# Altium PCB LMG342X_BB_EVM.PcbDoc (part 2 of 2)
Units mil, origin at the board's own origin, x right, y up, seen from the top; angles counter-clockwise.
Board outline 6400 x 3655 mil, 2 copper layers (Top Layer, Bottom Layer), stack 61.2 mil thick; 157 components, 63 nets, 278 pads, 411 vias.
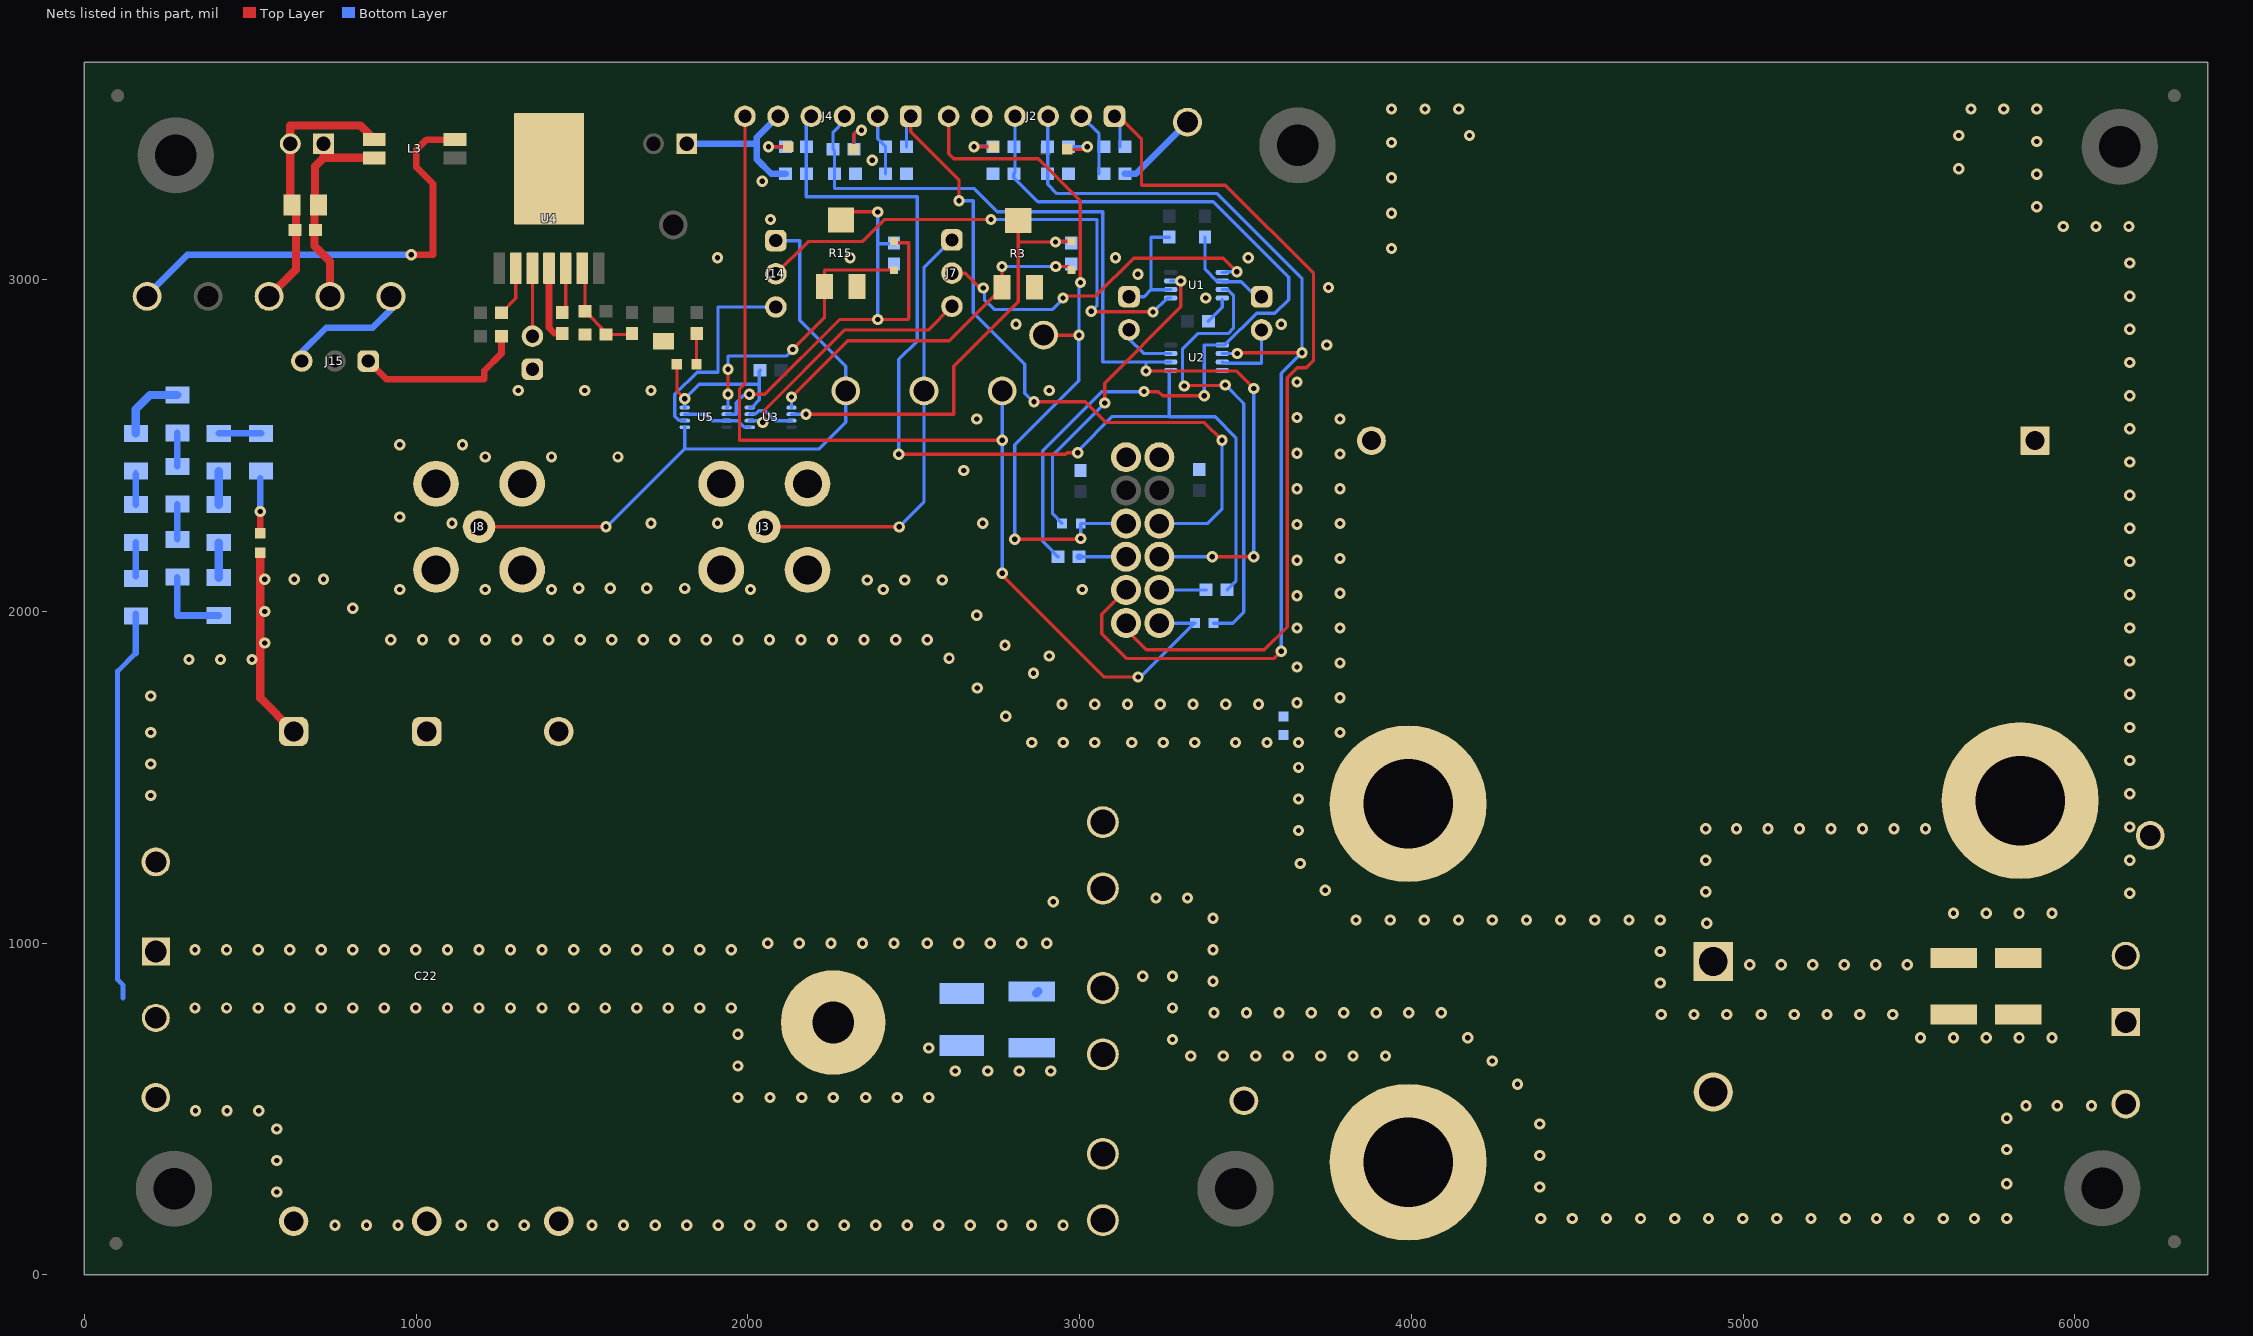
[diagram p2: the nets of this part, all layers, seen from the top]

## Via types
v1: diameter 34, hole 16, Top Layer to Bottom Layer, 411 vias

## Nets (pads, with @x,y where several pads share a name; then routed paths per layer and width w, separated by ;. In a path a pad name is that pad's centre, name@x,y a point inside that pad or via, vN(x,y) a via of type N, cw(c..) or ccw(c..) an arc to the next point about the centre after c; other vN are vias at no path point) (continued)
AGND: 5V_EN.2 AGND1.1 AGND2.1 C1.1 C2.1 C3.1 C5.2 C6.2 C8.2 C9.1 C10.2 C12.2 C14.2 C15.2 C17.2 C20.2 C21.2 C23.2 J2.5 J3.2 J3.3 J3.4 J3.5 J4.5 J8.2 J8.3 J8.4 J8.5 J12.1 J13.1 J15.1 J19.1 J25.1 L3.2 R9.1 R26.1 U1.4 U2.4 U3.4 U4.4 U4.8 U5.4 | length 3439.7
  Top Layer w10: 1416.97,2838.9 C20.2@1440.47,2838.9 ; 5V_EN.2@1785.94,2745 1785.94,2665.38 v1(1809.68,2641.65) v1@1809.68,2643.35
  Top Layer w20: J15.1@855.18,2755 910.18,2700 1205,2700 1205,2725.91 1256.97,2777.87 C15.2@1256.97,2830 ; v1(985,3075) 1050.47,3075 1050.47,3289.53 1000,3340 1000,3391.06 1031.5,3422.56 L3.2@1116.93,3422.56 ; U4.4@1400.47,3030 1400.47,2855.39 1416.97,2838.9
  Bottom Layer w10: U5.4@1809.68,2614.53 v1(1809.68,2641.65) 1853.03,2685 2034.28,2685 ; U3.4@2005.33,2614.53 2011.18,2614.53 2034.28,2637.63 2034.28,2685 ; C9.1@2036.83,2727.28 2034.28,2724.73 2034.28,2685 ; C1.1@3387.99,2875 3430,2917.01 U1.4@3430,2940
  Bottom Layer w20: AGND2.1@190,2955.02 309.98,3075 v1(985,3075) ; J12.1@1815.47,3410 2022.79,3410 ; J4.5@2091,3492.93 2029.03,3430.97 2027,3428.94 2027,3363 2070.42,3319.58 C14.2@2113.2,3319.58 ; C2.1@3136.5,3319.58 3169.58,3319.58 AGND1.1@3325,3475
  other v1: 2946.49,1720 3045.29,1720 3144.09,1720 3242.89,1720 3341.69,1720 3440.48,1720 3539.28,1720 3655,1725 2861.14,1813.56 3655,1832.44 2908,1866 2775,1898.56 3655.12,1949.99 2690,1988.56 3655.3,2047.33 950,2066.07 1208,2066 1408,2066 2008,2066 2408,2066 3008,2066 1490,2070.26 1585,2070.26 1695,2070.26 1809.68,2069.61 2359.68,2095.11 2472.9,2095.11 2586.12,2095.11 3655.3,2154.78 3655.3,2262.22 1108,2266 1708,2266 1908,2266 2708,2266 950,2284.55 3655.3,2369.66 2650.25,2424.79 1208,2466 1408,2466 1608,2466 3655.3,2477.11 950,2503.03 1139.58,2503.03 2690,2580 3655.3,2584.55 1308,2666 1508,2666 1708,2666 2908,2666 3655.3,2692 3745,2803.39 2808,2866 3608,2866 3380.32,2945.02 3750,2976.75 3175.56,3016.57 1908,3066 2308,3066 3108,3066 3508,3066 2067.96,3181.64 2043.37,3297.3 2374.49,3360.13
HS_FET_FAULTZ_2: C12.1 J2.4 R1.1 R7.2 U2.1 | length 2576.6
  Top Layer w10: v1(3194.13,2662.87) 3237.13,2662.87 3249.87,2650.13 v1(3375.49,2650.13)
  Bottom Layer w10: J2.4@2805,3492.93 2805,3323.08 C12.1@2801.5,3319.58 2801.5,3307.87 2874.37,3235 3402.25,3235 3630,3007.25 3630,2940 3588.76,2898.76 3533.41,2898.76 3438.04,2803.39 U2.1@3430,2803.39 3375.87,2803.39 3375.87,2650.5 v1(3375.49,2650.13) ; R7.2@2935,2165 2934.02,2165 2920.31,2178.7 2920.31,2179.69 2888.49,2211.52 2888.49,2484.8 3066.56,2662.87 v1(3194.13,2662.87)
HS_FET_OCZ_2: C5.1 J2.3 J23.1 R29.1 U2.2 | length 3224.6
  Top Layer w10: J23.1@3140,2065 3066.56,1991.56 3066.56,1932.9 3141.34,1858.13 3585.66,1858.13 v1(3607.6,1880.07) ; v1(3475,2777.8) 3477.2,2780 v1(3670,2780)
  Bottom Layer w10: J2.3@2905,3492.93 2903.5,3491.44 R29.1@2903.5,3401.05 C5.1@2903.5,3319.58 2903.5,3288.01 2931.51,3260 3415,3260 3670,3005 v1(3670,2780) 3607.6,2717.6 v1(3607.6,1880.07) ; U2.2@3430,2777.8 v1(3475,2777.8)
HS_FET_PWM_2: HS_FET_PWM.1 J2.6 J21.1 R2.2 | length 2167.2
  Top Layer w10: J2.6@2605,3492.93 2605,3380 2620,3365 2875.75,3365 3002.27,3238.49 v1(3002.27,2991.8) ; v1(2804.62,2218) 2805,2217.62 2805.38,2218 3003.54,2218 v1(3003.54,2219.82) ; HS_FET_PWM.1@2891.38,2833.13 v1(2997.99,2833.13)
  Bottom Layer w10: v1(2804.62,2218) 2804.62,2502.6 2997.01,2695 2997.01,2832.15 v1(2997.99,2833.13) 2997.99,2979.81 3004.47,2986.28 2998.95,2991.8 v1(3002.27,2991.8) ; v1(3003.54,2219.82) 3003.36,2220 R2.2@3003.36,2265 J21.1@3140,2265
HS_FET_TEMP_2: J2.1 J24.1 R8.1 | length 2649.2
  Top Layer w10: J2.1@3105,3492.93 3117.73,3492.93 3186.53,3424.14 3186.53,3285 3439,3285 3705,3019 3705,2757.57 3682.43,2735 3655.76,2735 3625.42,2704.67 3625.42,1953.23 3557.2,1885 3200.39,1885 3140,1945.39 J24.1@3140,1965
  Bottom Layer w10: J2.1@3105,3492.93 3121.5,3476.44 R8.1@3121.5,3401.05
HS_FET_TEMP_FILT_2: C2.2 J2.2 R8.2 | length 195.5
  Bottom Layer w10: J2.2@3005,3492.93 3058.5,3439.43 3058.5,3401.05 C2.2@3058.5,3319.58
HVBUS_2: C22.2 C22.4 CIN3.1 CIN4.1 HVBUS1.1 HVBUS2.1 HVIN.1 J1.2 R10.2 | length 1187
  Bottom Layer w15: 115.64,835 115.64,874.36 100,890 100,1820 154.92,1874.92
  Bottom Layer w20: 154.92,1874.92 R10.2@154.92,1992.78
  other v1: 755,150 850.1,150 945.19,150 1135.39,150 1230.49,150 1325.58,150 1530,150 1625.1,150 1720.19,150 1815.29,150 1910.39,150 2005.49,150 2100.58,150 2195,150 2290.1,150 2385.19,150 2480.29,150 2575.39,150 2670.49,150 2765.58,150 2855,150 2950.1,150 580,250 580,345.1 580,440.19 334.81,495 429.9,495 525,495 1969.74,535 2066.81,535 2161.9,535 2257,535 2354.81,535 2449.9,535 2545,535 2625,615 2722.81,615 2817.9,615 2913,615 1969.74,630.1 2545,684.19 1969.74,725.19 333.35,805 428.44,805 523.54,805 618.64,805 713.74,805 808.83,805 903.93,805 999.03,805 1094.13,805 1189.22,805 1284.32,805 1379.42,805 1474.51,805 1569.61,805 1664.71,805 1759.81,805 1854.9,805 1950,805
HVOUT_2: C25.1 COUT3.1 COUT4.1 HVOUT.1 J9.2 J18.1 L2.1
  other v1: 5020,935 5115,935 5210,935 5305,935 5400,935 5495,935 4890,1060 5634,1090 5733,1090 5832,1090 5931,1090 6165.5,1150.5 4887,1155 4887,1250 6165.5,1250.5 4887,1345 4980,1345 5075,1345 5170,1345 5265,1345 5360,1345 5455,1345 5550,1345 6165.5,1350.5 6165.5,1450.5 6165.5,1550.5 6165.5,1650.5 6165.5,1750.5 6165.5,1850.5 6165.5,1950.5 6165.5,2050.5 6165.5,2150.5 6165.5,2250.5 6165.5,2350.5 6165.5,2450.5 6165.5,2550.5 6165.5,2650.5 6165.5,2750.5 6165.5,2850.5 6165.5,2950.5 6165.5,3050.5 5965,3160.5 6064,3160.5 6163,3160.5 5885,3220 5885,3318.33 5650,3335 5885,3416.67 5650,3435 5687,3515 5786,3515 5885,3515
LS_FET_FAULTZ_2: C14.1 J4.4 R5.1 R21.2 U2.5 | length 3098.9
  Top Layer w10: v1(2455,2473.66) 2957.47,2473.66 2962.27,2478.47 v1(2994.47,2478.47)
  Bottom Layer w10: J4.4@2191,3492.93 2176.2,3478.13 R5.1@2176.2,3401.06 C14.1@2176.2,3319.58 2176.2,3250 2510,3250 2510,2814.76 2455,2759.76 v1(2455,2473.66) v1@2446.34,2465 ; v1(2994.47,2478.47) 2994.47,2483.63 3098.71,2587.87 3270,2587.87 ; U2.5@3274.49,2726.61 3275,2726.1 3270,2721.1 3270,2587.87 ; R21.2@3444.32,2065 3445.31,2065 3459.01,2078.7 3459.01,2079.69 3471.05,2091.72 3471.05,2524.26 3408.45,2586.85 3271.02,2586.85 3270,2587.87
LS_FET_OCZ_2: C21.1 J4.3 J28.1 R30.1 U2.6 | length 2895.7
  Top Layer w10: v1(3200,2725) 3472.34,2725 v1(3525,2672.34) ; v1(3400,2165) v1(3525,2165)
  Bottom Layer w10: J4.3@2291,3492.93 2291,3479.71 2256.47,3445.18 R30.1@2256.47,3392.93 2261,3388.41 C21.1@2261,3319.58 2261,3275 2681.82,3275 2751.82,3205 3070,3205 3070,2752.2 3200,2752.2 ; v1(3200,2725) 3200,2752.2 ; J28.1@3240,2165 v1(3400,2165) ; U2.6@3274.49,2752.2 3200,2752.2 ; v1(3525,2165) v1(3525,2672.34)
LS_FET_PWM_2: J4.6 J30.1 LS_FET_PWM.1 R4.2 | length 3217.8
  Top Layer w10: J4.6@1991,3492.93 1991,2686 1974.53,2669.53 1974.53,2515.78 v1(2766.51,2515.78) ; v1(2766.51,2115.3) 2766.51,2109.87 3073.99,1802.38 v1(3176.2,1802.38)
  Bottom Layer w10: v1(2766.51,2115.3) LS_FET_PWM.1@2766.51,2665 ; J30.1@3240,1965 R4.2@3345,1965 ; R4.2@3347.3,1965.01 R4.2@3345.01,1965.01 ; v1@3182.38,1802.38 v1(3176.2,1802.38) v1@3182.38,1802.38 ; v1@3182.38,1802.38 R4.2@3345,1965
LS_FET_TEMP_2: J4.1 J27.1 R27.1 | length 2167.1
  Top Layer w10: J4.1@2491,3492.93 2491,3446.01 2636.51,3300.5 v1(2636.51,3238.49) ; v1(2862.51,2632.17) 3016.79,2632.17 3079.47,2569.48 3375.59,2569.48 v1(3429.29,2515.78)
  Bottom Layer w10: R27.1@2477.83,3400.99 2477.83,3479.77 J4.1@2491,3492.93 ; v1(2636.51,3238.49) 2679.59,3238.49 2679.59,2900.57 2834.62,2745.54 2834.62,2658.1 v1@2861.53,2631.19 ; J27.1@3240,2265 3385.29,2265 3429.29,2309 v1(3429.29,2515.78)
LS_FET_TEMP_FILT_2: C3.2 J4.2 R27.2 | length 183.3
  Bottom Layer w10: J4.2@2391,3492.93 2391,3424.83 R27.2@2414.84,3400.99 C3.2@2414.84,3319.51
Net5V_EN_1: 5V_EN.1 R31.1 | length 93.7
  Top Layer w10: 5V_EN.1@1845,2745 1845,2838.03 R31.1@1845.47,2838.5
NetACMGND_1: ACMGND.1 C18.2 C19.2 J6.1 L3.4 | length 652.7
  Top Layer w25: J6.1@720.47,3410 720.47,3367.44 ; ACMGND.1@740.18,2950 740.18,3054.82 693.47,3101.53 693.47,3150 693.47,3213 C19.2@705.47,3225 695,3235.47 695,3341.97 720.47,3367.44 ; L3.4@874.02,3367.44 720.47,3367.44
NetC10_1: C10.1 D1.1 R3.2 U3.6 | length 1369.4
  Top Layer w10: v1(2174.84,2594.84) 2620,2594.84 2620,2739.17 2815,2934.17 2815,3115 ; R3.2@2815,3178.41 2815,3115 ; D1.1@2975,3116.1 2925,3116.1 v1(2927.14,3113.96) 2816.04,3113.96 2815,3115
  Bottom Layer w10: U3.6@2131.31,2594.84 v1(2174.84,2594.84) ; v1(2927.14,3113.96) 2975,3113.96 C10.1@2975,3111.01
NetC16_2: C16.2 R25.1 R26.2 U4.6 | length 323.4
  Top Layer w10: R25.1@1493.98,2902.44 R25.1@1506.02,2890.39 ; U4.6@1493.98,3023.5 1500.47,3030 1508.98,3021.5 1508.98,2905.39 R26.2@1571.97,2842.4 ; R26.2@1571.97,2835 1646.97,2835 C16.2@1650.47,2838.5
NetC20_1: C20.1 U4.5 | length 132.3
  Top Layer w10: C20.1@1440.47,2901.89 1450.47,2911.89 U4.5@1450.47,3030
NetC23_1: C23.1 D3.1 R15.2 U5.6 | length 1467.6
  Top Layer w10: v1(2004.4,2654.62) 2050.66,2654.62 2276.03,2880 v1(2391,2880) 2481.88,2880 2485,2883.12 2485,3111.4 2440,3111.4 D3.1@2440,3115.08 ; R15.2@2280,3180 2305,3205 2390,3205 v1(2391,3204)
  Bottom Layer w10: U5.6@1935.66,2594.84 1960.11,2594.84 1960.27,2595 1960.43,2594.84 1965.26,2594.84 1965.26,2630 1989.89,2654.62 v1(2004.4,2654.62) ; v1(2391,2880) 2391,3108.5 ; v1(2391,3204) 2391,3108.5 ; C23.1@2440.39,3111.01 2442.89,3108.5 2391,3108.5
NetD1_2: D1.2 R3.1 U3.5 | length 1080.8
  Top Layer w10: v1(2131.31,2646.31) 2301.3,2816.3 2607.08,2816.3 2765.79,2975.01 R3.1@2765.79,2977.62 2766.06,2977.9 v1(2766.06,3040) ; v1(2927.65,3040) 2964.49,3040 D1.2@2975,3029.49
  Bottom Layer w10: U3.5@2131.31,2614.53 v1(2131.31,2646.31) ; v1(2766.06,3040) v1(2927.65,3040)
NetD3_2: D3.2 R15.1 U5.5 | length 850
  Top Layer w10: v1(1940,2654.81) v1(1940,2730) ; v1(2135,2790) 2230.79,2885.79 R15.1@2230.79,2979.21 2230.79,3029.49 2440,3029.49 D3.2@2440,3028.47
  Bottom Layer w10: U5.5@1935.66,2614.53 1940,2618.86 v1(1940,2654.81) ; v1(1940,2730) 1940,2770 2115,2770 v1(2135,2790)
NetH13_1: H13.1
NetHS_FLT_2: HS_FLT.2 R1.2 | length 120.6
  Top Layer w10: v1(2681.47,3401.06) HS_FLT.2@2740.47,3401.06
  Bottom Layer w10: v1(2681.47,3401.06) 2679.59,3402.93 R1.2@2738.5,3402.93
NetHS_OC_2: HS_OC.2 R29.2 | length 130.8
  Top Layer w10: HS_OC.2@2962.48,3400.48 HS_OC.2@2962.48,3392.93 3015,3392.93 v1(3023.12,3401.05) v1@3025,3402.93
  Bottom Layer w10: R29.2@2966.5,3401.05 v1(3023.12,3401.05)
NetHVIN_EN_1: HVIN_EN.1 R20.1 | length 165.7
  Top Layer w20: v1(529.59,2301.3) 529.59,2236.79 HVIN_EN.1@530.06,2236.32
  Bottom Layer w20: v1(529.59,2301.3) R20.1@529.59,2401.79
NetJ7_2: J7.2 U1.1 | length 1060.9
  Top Layer w10: J7.2@2615,3020 2655,3020 2700,2975 v1(2709.47,2975) ; v1(2950,2945) 2956.25,2951.25 3048.85,2951.25 3162.6,3065 3433,3065 v1(3474,3024) v1@3475,3025
  Bottom Layer w10: v1(2709.47,2975) 2712.91,2971.55 2712.91,2940.08 2742.44,2910.55 2918.23,2910.55 v1@2951.34,2943.66 ; U1.1@3430,3021.77 3441.17,3021.77 3443.4,3024 v1(3474,3024)
  Bottom Layer w20: J7.2@2615,3020 J7.2@2625,3020
NetJ7_3: J7.3 U3.2 | length 775.7
  Top Layer w10: v1(2045,2570) 2045,2580 2048.64,2583.64 2048.64,2605.89 2291.1,2848.35 2543.35,2848.35 J7.3@2615,2920
  Bottom Layer w10: U3.2@2005.33,2575.16 2039.84,2575.16 v1(2045,2570)
NetJ10_1: J10.1 R6.2 U1.2 | length 301.6
  Bottom Layer w10: R6.2@3377.9,3128.5 3377.9,3031.73 3413.45,2996.18 U1.2@3430,2996.18 3432.06,2994.13 3487.64,2994.13 3533.01,2948.76 J10.1@3548.4,2948.76
NetJ10_2: J10.2 U2.3 | length 221
  Bottom Layer w10: U2.3@3430,2752.2 3434.28,2747.92 3548.4,2747.92 J10.2@3548.4,2848.76
NetJ11_1: J11.1 R22.1 U1.6 | length 348.2
  Bottom Layer w10: J11.1@3148.7,2949.13 3194.13,2949.13 3215,2970 ; R22.1@3270,3128.5 3215,3128.5 3215,2970 ; U1.6@3274.49,2970.59 3266.28,2970.59 3265.69,2970 3215,2970
NetJ11_2: J11.2 U2.7 | length 171
  Bottom Layer w10: J11.2@3148.7,2849.13 3148.7,2822.44 3193.34,2777.8 U2.7@3274.49,2777.8
NetJ13_2: J13.2 U4.3 | length 200
  Top Layer w10: J13.2@1350.47,2830 U4.3@1350.47,3030
NetJ14_2: J14.2 U1.5 | length 1579.9
  Top Layer w10: J14.2@2084.2,3018.02 2181.26,3115.08 2344.33,3115.08 2410.88,3181.64 v1(2732.93,3181.64) ; v1(3035,2905) 3036.22,2903.78 3214.58,2903.78 3213.39,2902.59 v1(3220.97,2902.59)
  Bottom Layer w10: v1(2732.93,3181.64) 3052.13,3181.64 3052.13,2922.13 v1(3035,2905) ; v1(3220.97,2902.59) 3263.39,2945 U1.5@3274.49,2945
NetJ14_3: J14.3 U5.2 | length 630.9
  Bottom Layer w10: U5.2@1809.68,2575.16 1809.68,2576.06 1792.06,2576.06 1779.81,2588.32 1779.81,2654.81 1846.55,2721.55 1910,2721.55 1910,2918.02 J14.3@2084.2,2918.02
NetJ16_1: J16.1 L2.2
  other v1: 3785,1635 3785,1740 3785,1845 3785,1950 3785,2055 3785,2160 3785,2265 3785,2370 3785,2475 3785,2580 3940,3094.29 3940,3200.71 3940,3307.14 3940,3413.57 4175,3435 3940,3515 4041.25,3515 4142.5,3515
NetJ22_1: J22.1 R7.1 | length 142
  Bottom Layer w10: R7.1@3000.92,2165 J22.1@3140,2165
  Bottom Layer w20: R7.1@2997.99,2165 R7.1@3000.92,2165
NetJ29_1: J29.1 R21.1 | length 141.3
  Bottom Layer w10: J29.1@3240,2065 R21.1@3381.33,2065
NetLS_FLT_2: LS_FLT.2 R5.2 | length 113.6
  Top Layer w10: v1@2060,3402.93 v1(2061.87,3401.06) LS_FLT.2@2121.47,3401.06
  Bottom Layer w10: v1(2061.87,3401.06) R5.2@2113.2,3401.06
NetLS_OC_2: LS_OC.2 R30.2 | length 155.9
  Top Layer w10: LS_OC.2@2310.21,3393.77 LS_OC.2@2318.48,3393.77 ; LS_OC.2@2318.48,3392.93 LS_OC.2@2318.48,3393.77 ; v1(2342.1,3450.76) 2330.8,3450.76 2318.48,3438.44 LS_OC.2@2318.48,3393.77
  Bottom Layer w10: R30.2@2319.46,3392.93 2319.46,3438.44 2331.78,3450.76 v1(2342.1,3450.76)
  Bottom Layer w20: R30.2@2319.32,3392.93 R30.2@2319.46,3392.93
NetR2_1: R2.1 U1.7 | length 933
  Top Layer w10: v1(3075.4,2628.38) 3075.4,2688.42 3305,2918.02 v1(3305,2996.18)
  Bottom Layer w10: R2.1@2946.67,2265.69 2918.23,2294.14 2918.23,2471.21 v1(3075.4,2628.38) ; U1.7@3274.49,2996.18 v1(3305,2996.18)
NetR3_3: R3.3
NetR4_1: R4.1 U1.3 | length 1371.7
  Top Layer w10: v1(3315,2680) 3316.49,2681.49 3437.51,2681.49 v1(3439,2682.98)
  Bottom Layer w10: v1(3315,2680) 3310.13,2684.87 3310.13,2791.7 3356.26,2837.83 3447.21,2837.83 3463.54,2854.17 3463.54,2953.59 3446.55,2970.59 U1.3@3430,2970.59 ; R4.1@3403.3,1965.01 3461.76,1965.01 3495,1998.24 3495,2626.98 v1(3439,2682.98)
NetR10_1: R10.1 R16.2 | length 100.8
  Bottom Layer w20: R10.1@154.92,2106.95 R16.2@154.92,2207.78
NetR11_1: R11.1 R17.2 | length 215.7
  Bottom Layer w25: R17.2@154.92,2536.95 154.92,2609.92 197.62,2652.62 R11.1@279.92,2652.62
NetR11_2: R11.2 R12.2 | length 100.8
  Bottom Layer w20: R12.2@279.92,2437.62 R11.2@279.92,2538.45
NetR12_1: R12.1 R18.2 | length 105.8
  Bottom Layer w20: R18.2@279.92,2217.62 R12.1@279.92,2323.45
NetR13_1: R13.1 R19.2 | length 105.8
  Bottom Layer w25: R19.2@404.92,2101.95 R13.1@404.92,2207.78
NetR13_2: R13.2 R14.2 | length 100.8
  Bottom Layer w25: R13.2@404.92,2321.95 R14.2@404.92,2422.78
NetR14_1: R14.1 R20.2 | length 127.2
  Bottom Layer w20: R14.1@404.92,2536.95 405.06,2537.09 R20.2@532.05,2537.09
NetR15_3: R15.3
NetR16_1: R16.1 R17.1 | length 100.8
  Bottom Layer w10: R17.1@154.92,2412.96 R17.1@154.92,2422.78
  Bottom Layer w20: R16.1@154.92,2321.95 R17.1@154.92,2412.96
NetR18_1: R18.1 R19.1 | length 240.7
  Bottom Layer w20: R18.1@279.92,2103.45 279.92,1987.78 R19.1@404.92,1987.78
NetR28_2: R28.2 U4.2 | length 145.3
  Top Layer w10: R28.2@1258.62,2902.05 1300.47,2943.9 U4.2@1300.47,3030
NetU3_1: U3.1 U5.3 U5.7 | length 212.5
  Bottom Layer w10: U5.3@1809.68,2594.84 1872.83,2594.84 1892.51,2575.16 U5.7@1935.66,2575.16 1935.82,2575 1969.09,2575 1987.71,2556.38 2005.33,2556.38 U3.1@2005.33,2555.47
NetU3_3: U3.3 U3.7 | length 142.4
  Bottom Layer w10: U3.3@2005.33,2594.84 2006.24,2595.75 2022.95,2595.75 2032.08,2604.87 2052.37,2604.87 2082.09,2575.16 U3.7@2131.31,2575.16
PGND: C22.1 C22.3 C25.2 CIN3.2 CIN4.2 COUT3.2 COUT4.2 HVIN_EN.2 J1.1 J9.1 PGND1.1 PGND2.1 PGND4.1 PGND5.1 R9.2 | length 611.7
  Top Layer w25: PGND5.1@215,1245 PGND5.1@237.2,1245 ; HVIN_EN.2@530.06,2177.27 530.06,1738.52 C22.1@630.39,1638.19
  Bottom Layer w25: CIN3.2@2868.74,848.74 CIN3.2@2875,855
  other v1: 4390,170 4485,170 4588,170 4691,170 4794,170 4895.75,170 4998.75,170 5101.75,170 5204.75,170 5307.75,170 5402,170 5500,170 5603,170 5697.25,170 5795,170 4387,265 5795,275 4387,360 5795,378 4387,455 5795,472.25 5852.75,510 5947,510 6050,510 4320,575 4243.75,645 4170,715 5535,715 5634,715 5733,715 5832,715 5931,715 4753,785 4852,785 4951,785 5055,785 5154,785 5253,785 5352,785 5451,785 3405,790 3502.86,790 3600.71,790 3698.57,790 3796.43,790 3894.29,790 3992.14,790 4090,790 4750,880 3402,885 4750,975 333.35,980 428.44,980 523.54,980 618.64,980 713.74,980 808.83,980 903.93,980 999.03,980 1094.13,980 1189.22,980 1284.32,980 1379.42,980 1474.51,980 1569.61,980 1664.71,980 1759.81,980 1854.9,980 1950,980 3402,980 2060,1000 2155.1,1000 2250.19,1000 2345.29,1000 2440.39,1000 2540.32,1000 2635.42,1000 2730.52,1000 2825.61,1000 2900.61,1000 3833,1070 3936,1070 4039,1070 4142,1070 4243.75,1070 4346.75,1070 4449.75,1070 4552.75,1070 4655.75,1070 4750,1070 3402,1075 2920.71,1125 3230,1136.46 3325.1,1136.46 3740,1160 3665,1240 3660,1340 3660,1435 200,1445 3660,1530 200,1540 2855.36,1605 2950.36,1605 3045.36,1605 3157.06,1605 3252.06,1605 3347.06,1605 3470,1605 3565,1605 3660,1605 200,1635 2777.61,1684.06 200,1745 2691.47,1769.06 315,1855 410.1,1855 505.19,1855 2606.47,1859.06 543.84,1905 923.67,1915 1018.77,1915 1113.86,1915 1208.96,1915 1304.06,1915 1399.16,1915 1494.25,1915 1589.35,1915 1684.45,1915 1779.54,1915 1874.64,1915 1969.74,1915 2064.84,1915 2159.93,1915 2255.03,1915 2350.13,1915 2445.22,1915 2540.32,1915 543.84,2000 808.67,2010 543.84,2097.41 632.2,2097.41 720.57,2097.41
PWM_HS_2: J3.1 J7.1 PWM_HS.1 | length 1342.1
  Top Layer w10: J3.1@2049.53,2255.26 2049.66,2255.13 2455.68,2255.13 v1(2455.81,2255)
  Bottom Layer w10: v1(2455.81,2255) 2530.76,2329.94 2530.76,2653.49 PWM_HS.1@2525,2659.24 ; PWM_HS.1@2530.76,2665 2530.76,3035.76 J7.1@2615,3120
  Bottom Layer w20: PWM_HS.1@2525,2659.24 PWM_HS.1@2530.76,2665
PWM_LS_2: J8.1 J14.1 PWM_LS.1 U5.1 | length 1978.8
  Top Layer w10: J8.1@1189.71,2255 1189.97,2255.26 v1(1571.97,2255.26)
  Top Layer w20: J8.1@1189.45,2255.26 J8.1@1189.71,2255
  Bottom Layer w10: v1(1571.97,2255.26) 1574.94,2255.26 1809.68,2490 ; U5.1@1809.68,2555.47 1809.68,2490 ; J14.1@2084.2,3118.02 2155.92,3118.02 2155.92,2877.8 2295,2738.72 PWM_LS.1@2295,2665 2295,2570.18 2214.82,2490 1809.68,2490
SW_2: J17.1 SW1.1 SW2.1 SW.1 | length 116.6
  Bottom Layer w25: SW1.1@3070,665 SW1.1@3085,650 ; J17.1@4045,345 J17.1@4045,440.39
  other v1: 3335,660 3432.86,660 3530.71,660 3628.57,660 3726.43,660 3824.29,660 3922.14,660 3280,710 3280,805 3190,900 3280,900
TACH_2: J15.3 TACH.1 | length 360.1
  Bottom Layer w20: J15.3@656.14,2782.83 728.7,2855.39 868.7,2855.39 923.93,2910.62 TACH.1@923.93,2950
VAUX_2: C18.1 C19.1 J6.2 L3.3 VAUX.1 | length 827.4
  Top Layer w25: VAUX.1@556.43,2950 636.4,3029.97 ; 637.47,3029.97 637.47,3150 637.47,3213 C19.1@625.47,3225 620.47,3230 J6.2@620.47,3410 620.47,3464.18 619.65,3465 831.57,3465 L3.3@874.02,3422.56
pads on no net: FID1.1 FID2.1 FID3.1 FID4.1 FID5.1 FID6.1 FID7.1 FID8.1 H2.1 H3.1 H4.1 H5.1 H6.1 H7.1 H14.0 LBL1.0 SH-J1.0 SH-J2.0 SH-J3.0 SH-J4.0 SH-J5.0

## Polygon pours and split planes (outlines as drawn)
AGND on Bottom Layer "Bottom Layer-AGND" (solid, pour order 18): 1871.41,3537.51 3388.47,3537.51 3388.47,3377.89 3775,2991.36 3775,2788.61 3678.42,2692.03 3678.42,1682.51 2924.57,1682.51 2839.57,1767.51 2577.12,2029.96 916.41,2029.96 916.41,2542.51 1162.97,2542.51 1162.97,2705.19 1394.41,2705.19 1394.41,2847.51 1518.42,2847.51 1518.42,2788.23 1684,2788.23 1684,2827.51 1871.41,2827.51
NetJ16_1 on Bottom Layer "Bottom Layer-NetJ16_1" (solid, pour order 40): 3755,1348.07 3755,2590 3920,2778.13 3920,3542.93 4225,3542.93 4225,1185 3872.65,1185 3755,1348.07 3872.65,1185
PGND on Bottom Layer "Bottom Layer-PGND" (solid, pour order 36): 174.61,930.02 2015,932 2015,970 2500,970 2500,815 2924.57,815 2924.57,1085 3370,1085 3370,750 4080,750 4355,475 4355,130 5820,130 5820,475 6200,475 6200,815 4785,815 4785,1105 3840,1105 3690,1255 3689.96,1630 2883.35,1630 2561.08,1952.27 915,1952.27 725,2125 516.28,2125 516.28,1885 299.63,1885 174.61,1759.98
HVBUS_2 on Bottom Layer "Bottom Layer-HVBUS" (solid, pour order 6): 100,835 100,460 540,460 540,100 3155,100 3155,400 2925,630 2925,720 2500,720 2500,565 2015,565 2015,835
HVOUT_2 on Bottom Layer "Bottom Layer-HVOUT" (solid, pour order 42): 5595,3545 5595,1395 4855,1395 4855,900 6205,900 6205,1280 6275,1280 6275,1370 6200,1370 6200,3195 5915,3195 5915,3545
SW_2 on Bottom Layer "Bottom Layer-SW" (solid, pour order 38): 2995,935 3305,935 3305,685 3980,685 4230,435 4230,115 3900.49,115 3879.51,115 3730,264.51 3730,440 3210.52,440 2995,661.98
AGND on Top Layer "Bottom Layer-AGND" (solid, pour order 43): 1871.41,3537.51 3387.94,3537.51 3388.47,3377.89 3775,2991.36 3775,2788.61 3678.39,2692 3678.39,1682.51 2924.57,1682.51 2839.57,1767.51 2577.12,2029.96 916.41,2029.96 916.41,2542.51 1162.97,2542.51 1162.97,2705.19 1394.41,2705.19 1394.41,2847.51 1518.42,2847.51 1518.42,2788.23 1684,2788.23 1684,2827.51 1871.41,2827.51 1871.41,3515
AGND on Top Layer "Bottom Layer-AGND" (solid, pour order 22): 1871.41,3537.51 3387.94,3537.51 3388.47,3377.89 3775,2991.36 3775,2788.61 3678.39,2692 3678.39,1682.51 2924.57,1682.51 2839.57,1767.51 2577.12,2029.96 916.41,2029.96 916.41,2542.51 1162.97,2542.51 1162.97,2705.19 1394.41,2705.19 1394.41,2847.51 1518.42,2847.51 1518.42,2788.23 1684,2788.23 1684,2827.51 1871.41,2827.51 1871.41,3515
NetJ16_1 on Top Layer "Top Layer-NetJ16_1" (solid, pour order 32): 3755,1348.07 3755,2590 3920,2778.13 3920,3542.93 4225,3542.93 4225,1185 3872.65,1185 3755,1348.07 3872.65,1185
PGND on Top Layer "Top Layer-PGND" (solid, pour order 28): 174.61,930.02 2015,930.02 2015,970 2500,970 2500,815 2925,815 2925,1085 3370,1085 3370,750 4080,750 4355,475 4355,130 5820,130 5820,475 6200,475 6200,815 4785,815 4785,1105 3840,1105 3690,1255 3689.96,1630 2883.35,1630 2561.08,1952.27 915,1952.27 725,2125 516.28,2125 516.28,1885 299.63,1885 174.61,1759.98
SW_2 on Top Layer "Top Layer-SW" (solid, pour order 34): 2995,935 3305,935 3305,685 3980,685 4230,435 4230,115 3900.49,115 3879.51,115 3730,264.51 3730,440 3210.52,440 2995,661.98
HVOUT_2 on Top Layer "Top Layer-HVOUT" (solid, pour order 30): 5595,3545 5595,1395 4855.55,1395 4855.55,900 6205,900 6205,1280 6275,1280 6275,1370 6200,1370 6200,3195 5915,3195 5915,3545
AGND on Top Layer "Top Layer-AGND" (solid, pour order 10): 1149.74,3442.94 1246.8,3540 1645,3540 1845.06,3540 1845.71,3380 1787.16,3378.49 1785.98,3449.02 1645,3450 1645,3144.61 1449.67,3144.61 1413.5,3080 1385.06,3080 1335,3144.61 1199.74,3144.61 1199.74,3263.02 1199.74,3375 1199.74,3355.47 1149.74,3405.47
HVBUS_2 on Top Layer "Top Layer-HVBUS" (solid, pour order 0): 100,835 100,460 540,460 540,100 3155,100 3155,400 2925,630 2925,720 2500,720 2500,565 2015,565 2015,835

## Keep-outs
Keep-Out Layer:
  lines w3.94: -1.97,3500 cw(c0,3500) 0,3501.97 ccw(c0,3500) -1.97,3500 ; 6400,-1.97 ccw(c6400,0) 6401.97,0 cw(c6400,0) 6400,-1.97
  lines w47.24: 6400,0 0,0 0,3655 6400,3655
  text ".Layer_Name" at 577,-858.49 h60

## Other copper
Top Layer:
  text ".Layer_Name" at 577,-858.49 h60
Bottom Layer:
  text ".Layer_Name" at 577,-858.49 h60

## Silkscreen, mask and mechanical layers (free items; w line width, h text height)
Top Overlay:
  region: 1485.56,752.99 1185.56,752.99 1185.56,652.99 1485.56,652.99
  text "+ 12V -" at 535,3570 h40
  text "+ 5V -" at 1646.97,3570 h40
  text "1" at 2481.72,3570 h40
  text "1" at 3100,3570 h40
  text "1" at 2679.59,3100 h40
  text "1" at 2007.59,3098.21 h40
  text "AGND" at 437.36,2777.8 h40
  text "TACH" at 187.36,2772.8 h40
  text "12V" at 332.28,2702.8 h40
  text "1" at 846.82,2651.68 h40
  text "PWM_LS" at 1425.48,2405 h40
  text "PWM_HS" at 2285,2400.2 h40
  text "200V" at 6200,1170 h40
  text "13A" at 6220,1095 h40
  text "HV+" at 5975,1080 h40
  text "7A" at 685,848.74 h40 r90
  text "400V" at 3161.87,835 h40
  text "400V" at 590,790 h40 r90
  text "13A" at 3190,740 h40
  text "+ HVIN -" at 495,715 h40 r90
  text ".PCB_Rev" at 1005.56,673 h60
  text "-" at 1115.56,673 h60
  text "HV-" at 5970,605 h40
  text "LMG342X-BB-EVM / HVP049A1" at 5095,490 h40
  text "Caution" at 2139.7,414 h60
  text "LMG342XX-BB-EVM" at 855,345.1 h60
  text "High Voltage" at 2004.7,319 h60
  text "400V" at 2805.61,305 h40
  text "Op V: 520V" at 2054.7,214 h60
  text "7A" at 2864.35,210 h40
  text "SW" at 3950,40 h40
  text ".Layer_Name" at 577,-858.49 h60
Bottom Overlay:
  text ".Layer_Name" at 577,-858.49 h60
Top Paste:
  text ".Layer_Name" at 577,-858.49 h60
Bottom Paste:
  text ".Layer_Name" at 577,-858.49 h60
Top Solder:
  text ".Layer_Name" at 577,-858.49 h60
  text ".Layer_Name" at 577,-858.49 h60
Bottom Solder:
  text ".Layer_Name" at 577,-858.49 h60
Drill Guide:
  text ".Layer_Name" at 577,-858.49 h60
M1 Board Outline:
  the board outline again, w47.24
  text ".Layer_Name" at 577,-858.49 h60
M2 Board Dimensions:
  rectangle: 125,-400 500,-275
  rectangle: 0,-275 125,-150
  lines w7: 0,-275 1000,-275 ; 125,-400 125,-150 ; 250,-400 250,-150 ; 500,-400 500,-150 ; 750,-400 750,-150 ; 0,-400 0,-150 1000,-150 1000,-400 0,-400
  text ".Layer_Name" at 577,-858.49 h60
M3 3D STEP Top:
  text ".Layer_Name" at 577,-858.49 h60
M4 3D STEP Bottom:
  text ".Layer_Name" at 577,-858.49 h60
M5 Assembly Top:
  lines w10: -292,-930.17 6308,-930.17 ; -292,-726.83 6310,-726.83 ; -292,-523.5 -292,-1133.5 3713,-1133.5 6310,-1133.5 6310,-523.5 -291.5,-523.5 -291.5,-1133.5 1284,-1133.5 ; 2173,-1133.5 2173,-523.5 ; 3440,-726.83 3440,-523.5 ; 4280,-726.83 4280,-523.5 ; 4902,-1140 4902,-937.17
  text "COMPONENTS MARKED 'DNP' SHOULD NOT BE POPULATED." at 1153.5,-318.5 h60
  text "ASSEMBLY VARIANT:" at 1153,-434 h60
  text ".VariantName" at 2189,-434 h60
  text "PCB VIEWED FROM TOP SIDE" at -228.5,-655.67 h60
  text "BOARD #:" at 2248,-655.67 h60
  text ".PRJ_Number" at 2793.5,-655.67 h60
  text "REV:" at 3638,-655.67 h60
  text ".PCB_Rev" at 3929.5,-655.67 h60
  text "SVN REV:" at 4476,-655.67 h60
  text ".VersionControl_RevNumber" at 4982,-655.67 h60
  text "TID #:" at 2248,-859 h60
  text ".TID" at 2793.5,-859 h60
  text "PLOT NAME =" at -228.5,-1064.34 h60
  text ".plot_File_Name" at 577,-1064.34 h60
  text "GENERATED    :" at 2250,-1064.34 h60
  text ".Print_Date" at 3119.5,-1064.34 h60
  text ".Print_Time" at 3848.5,-1064.34 h60
  text "TEXAS INSTRUMENTS" at 5113,-1064.34 h60
M6 Assembly Bottom:
  lines w10: -292.5,-727.33 6309.5,-727.33 ; -290.5,-930.67 6309.5,-930.67 ; 1115.5,-1140.5 1115.5,-937.67 ; 1737.5,-727.33 1737.5,-524 ; 2577.5,-727.33 2577.5,-524 ; 3844.5,-1134 3844.5,-524 ; 4733.5,-1134 6309,-1134 6309,-524 -292.5,-524 -292.5,-1134 2304.5,-1134 6309.5,-1134 6309.5,-524
  text "COMPONENTS MARKED 'DNP' SHOULD NOT BE POPULATED." at 6102,-318 h60
  text ".VariantName" at 5058,-434 h60
  text "ASSEMBLY VARIANT:" at 6097,-434 h60
  text ".VersionControl_RevNumber" at 1035.5,-656.17 h60
  text "SVN REV:" at 1541.5,-656.17 h60
  text ".PCB_Rev" at 2088,-656.17 h60
  text "REV:" at 2379.5,-656.17 h60
  text ".PRJ_Number" at 3224,-656.17 h60
  text "BOARD #:" at 3769.5,-656.17 h60
  text "PCB VIEWED FROM BOTTOM SIDE" at 6246,-656.17 h60
  text ".TID" at 3224,-859.5 h60
  text "TID #:" at 3769.5,-859.5 h60
  text "TEXAS INSTRUMENTS" at 904.5,-1064.84 h60
  text ".Print_Time" at 2169,-1064.84 h60
  text ".Print_Date" at 2898,-1064.84 h60
  text "GENERATED    :" at 3767.5,-1064.84 h60
  text ".plot_File_Name" at 5440.5,-1064.84 h60
  text "PLOT NAME =" at 6246,-1064.84 h60
M9 Title Sheet:
  drawing of 57 lines, arcs and shapes, not listed
  text "1" at 739.84,8036.5 h70
  text "2" at 3235.5,8036.5 h70
  text "3" at 5724.84,8036.5 h70
  text "4" at 8231.51,8036.5 h70
  text "5" at 10730.5,8036.5 h70
  text "6" at 13235.5,8036.5 h70
  text "A" at -416.5,6893.5 h70
  text "A" at 14383.5,6893.5 h70
  text "B" at -416.5,4513.5 h70
  text "B" at 14383.5,4513.5 h70
  text "C" at -416.5,2138.5 h70
  text "C" at 14383.5,2138.5 h70
  text "PROJECT TITLE:" at 11343.5,277.5 h45
  text ".PRJ_Title" at 11393.5,144.17 h70
  text "DESIGNED FOR:" at 11343.5,-23.5 h45
  text ".PRJ_Customer" at 11393.5,-163.5 h70
  text "D" at -416.5,-231.5 h70
  text "D" at 14383.5,-231.5 h70
  text "FILE NAME:" at 11343.5,-323.5 h45
  text ".PCB_File_Name_No_Path" at 11393.5,-443.5 h70
  text "Texas Instruments (TI) and/or its licensors do not warrant the accuracy or completeness of this specification" at 6374,-605.34 h45
  text "ENGINEER:" at 11343.5,-613.5 h45
  text "LAYOUT BY:" at 12848.5,-613.5 h45
  text "or any information contained therein. TI and/or its licensors do not warrant that this design will meet" at 6329.01,-718 h45
  text ".PRJ_Engineer" at 11393.5,-768.49 h70
  text ".PCB_Layout" at 12899,-768.49 h70
  text "the specifications, will be suitable for your application or fit for any particular purpose, or will operate in" at 6329.01,-830.67 h45
  text ".Layer_Name" at 577,-858.49 h60
  text "ALTIUM DESIGNER VERSION:" at 12848.5,-923.5 h45
  text "an implementation. TI and/or its licensors do not warrant that the design is production worthy. You should" at 6329.01,-943.33 h45
  text "completely validate and test your design implementation to confirm the system functionality for your application." at 6374,-1056 h45
  text ".print_Scale" at 11393.5,-1056.83 h70
  text ".Application_BuildNumber" at 12899,-1056.83 h70
  text "1" at 739.84,-1263.5 h70
  text "2" at 3235.5,-1263.5 h70
  text "3" at 5724.84,-1263.5 h70
  text "4" at 8231.51,-1263.5 h70
  text "5" at 10730.5,-1263.5 h70
  text "6" at 13235.5,-1263.5 h70
M10 Fab Notes:
  drawing of 185 lines, arcs and shapes, not listed
  text "DESIGN INFORMATION" at 12381.02,5910 h60
  text "MIN. TRACK WIDTH:" at 11736.46,5730 h60
  text "8" at 12832.7,5730 h60
  text "MIL" at 12987.46,5730 h60
  text "MIN. CLEARANCE:" at 11736.46,5598 h60
  text "0.2" at 12772.7,5598 h60
  text "mm" at 12987.46,5598 h60
  text "MIN. VIA PAD SIZE:" at 11736.46,5466 h60
  text "20" at 12802.71,5466 h60
  text "MIL" at 12987.46,5466 h60
  text "0.05mm (2MIL)" at 12431.46,5324.29 h60
  text "MINIMUM ANNULAR RING" at 11407.23,5320 h60
  text "EXTERNAL" at 13139.46,5320 h60
  text "PER" at 11607.23,5202 h60
  text "IPC-D-275 CLASS 2 LEVEL C" at 11827.23,5202 h60
  text "MIL, HOLES" at 13315.46,5089.71 h60
  text "+/-" at 12923,5089 h60
  text "+/-" at 13777,5089 h60
  text "REGISTRATION TOLERANCES:" at 11407.23,5084 h60
  text "METAL" at 12607,5084 h60
  text "5" at 13183.2,5084 h60
  text "3" at 14016.2,5084 h60
  text "MIL" at 14132.46,5084 h60
  text "MATERIAL:" at 11332.46,4874.54 h60
  text "FR-4 High Tg" at 12318.9,4734.21 h60
  text "FR-408" at 11753.46,4725.64 h60
  text "X" at 12165.46,4725.64 h60
  text "OTHER" at 13241.46,4725.64 h60
  text "62 MIL (1.6mm) +/-10%" at 12073.56,4562.92 h60
  text "THICKNESS:" at 11407.23,4558.64 h60
  text "X" at 11945.4,4558.64 h60
  text "OTHER" at 13358.46,4558.64 h60
  text "TOLERANCE:" at 11407.23,4400.64 h60
  text "X" at 12246.53,4400.64 h60
  text "ANSI IPC-6012 TYPE 3 CLASS 2" at 12433.48,4400.64 h60
  text "OTHER +/-" at 12433.46,4244.64 h60
  text "BOW & TWIST:" at 11407.23,4087.64 h60
  text "X" at 12246.53,4087.64 h60
  text "ANSI IPC-6012 TYPE 3 CLASS 2" at 12433.48,4087.64 h60
  text "OTHER +/-" at 12433.46,3929.13 h60
  text "DRILLING:" at 11332.46,3790.64 h60
  text "REFERENCE:" at 11407.23,3673.64 h60
  text "X" at 12055.46,3673.64 h60
  text "AS SHOWN" at 12242.46,3673.64 h60
  text "X" at 12956.46,3673.64 h60
  text "NC_DRILL FILES" at 13093.46,3673.64 h60
  text "PTH MIN COPPER THICKNESS:" at 11407.23,3515.64 h60
  text "X" at 12749.46,3515.64 h60
  text "1MIL" at 12894.46,3515.64 h60
  text "OTHER" at 13391.46,3515.64 h60
  text "BOARD FINISH:" at 11332.46,3356.64 h60
  text "SILKSCREEN:" at 11487.68,3238.64 h60
  text "X" at 12436.46,3238.64 h60
  text "TOP" at 12562.46,3238.64 h60
  text "X" at 12946.46,3238.64 h60
  text "BOTTOM" at 13073.46,3238.64 h60
  text "SILKSCREEN COLOR:" at 11487.68,3071.64 h60
  text "X" at 12435.42,3071.64 h60
  text "WHITE" at 12562.46,3071.64 h60
  text "OTHER" at 13073.46,3071.64 h60
  text "SOLDER RESIST COLOR:" at 11487.68,2901.64 h60
  text "X" at 12055.42,2742.44 h60
  text "GREEN" at 12182.46,2742.44 h60
  text "BLUE" at 12773.46,2742.44 h60
  text "OTHER" at 13311.46,2742.44 h60
  text "IMMERSION GOLD (ENIG)" at 12393.46,2553.92 h60
  text "ENEPIG" at 13731,2550.64 h60
  text "SURFACE FINISH:" at 11332.46,2549.64 h60
  text "X" at 12206.51,2549.64 h60
  text "IMM. TIN/SILVER OR EQUIV" at 11662,2392.64 h60
  text "OTHER" at 13093.46,2392.64 h60
  text "ARRAY/PANEL:" at 11332.46,2213.64 h60
  text "CUT AND TRIM PER MECH LAYER 1" at 12393.46,2209.35 h60
  text "N.C. ROUTE" at 12393.46,2057.64 h60
  text "X" at 13072.46,2057.64 h60
  text "V. SCORE" at 13259.46,2057.64 h60
  text "CERTIFICATION:" at 11332.46,1920.64 h60
  text "MATERIALS AND WORKMANSHIP FOR ALL PCBS" at 12057.46,1920.64 h60
  text "TO MEET OR EXCEED THE REQUIREMENTS OF:" at 12057.46,1822.64 h60
  text "X" at 11683.96,1686.13 h60
  text "ANSI IPC-A-600F CLASS ->" at 11822.96,1686.13 h60
  text "X" at 13462.02,1686.13 h60
  text "2" at 13580.96,1686.14 h60
  text "1" at 13265.96,1684.64 h60
  text "3" at 13934.96,1684.64 h60
  text "X" at 11686.02,1526.64 h60
  text "UL 94V-0" at 11822.96,1526.64 h60
  text "X" at 12498.02,1526.64 h60
  text "RoHS" at 12634.96,1526.64 h60
  text "OTHER" at 13279.36,1526.64 h60
  text "PER ORDER" at 13676.42,1526.64 h60
  text "ADDITIONAL REQUIREMENTS:" at 11332.46,1385.64 h60
  text "MICROSECTION:" at 11407.23,1270.64 h60
  text "YES" at 12312.96,1270.64 h60
  text "REQUIRED" at 13174.46,1114.49 h60
  text "BARE BOARD ELEC. TEST:" at 11407.23,1111.64 h60
  text "NONE" at 12712.96,1111.64 h60
  text "X" at 13047.46,1111.64 h60
  text "PER ORDER" at 13766.46,1111.64 h60
  text "MANUFACTURER'S UL:" at 11407.23,954.64 h60
  text "RAIL" at 12572.96,950.35 h60
  text "METAL" at 13064.77,950.35 h60
  text "X" at 13440,950 h60
  text "SILK" at 13576.46,950.35 h60
  text ".Layer_Name" at 577,-858.49 h60
M11 Gerber Information:
  lines w10: -292,-930.17 6308,-930.17 ; -292,-726.83 6310,-726.83 ; -292,-523.5 -292,-1133.5 3713,-1133.5 6310,-1133.5 6310,-523.5 -291.5,-523.5 -291.5,-1133.5 1284,-1133.5 ; 2173,-1133.5 2173,-523.5 ; 3440,-726.83 3440,-523.5 ; 4280,-726.83 4280,-523.5 ; 4902,-1140 4902,-937.17
  text "ALL ARTWORK VIEWED FROM TOP SIDE" at -228.5,-655.67 h60
  text "BOARD #:" at 2248,-655.67 h60
  text ".PRJ_Number" at 2793.5,-655.67 h60
  text "REV:" at 3638,-655.67 h60
  text ".PCB_Rev" at 3929.5,-655.67 h60
  text "SVN REV:" at 4476,-655.67 h60
  text ".VersionControl_RevNumber" at 4982,-655.67 h60
  text "LAYER NAME =" at -228.5,-858.49 h60
  text "TID #:" at 2248,-859 h60
  text ".TID" at 2793.5,-859 h60
  text "PLOT NAME =" at -228.5,-1064.34 h60
  text ".plot_File_Name" at 577,-1064.34 h60
  text "GENERATED    :" at 2250,-1064.34 h60
  text ".Print_Date" at 3119.5,-1064.34 h60
  text ".Print_Time" at 3848.5,-1064.34 h60
  text "TEXAS INSTRUMENTS" at 5113,-1064.34 h60
M12 Stackup:
  drawing of 191 lines, arcs and shapes, not listed
  text "Layer" at 9807.84,7087.5 h60
  text "Name" at 10217.76,7087.5 h60
  text "Material" at 11147.5,7087.5 h60
  text "Thickness" at 12007.27,7087.5 h60
  text "Constant" at 12657.1,7087.5 h60
  text "Board Layer Stack" at 13226.96,7087.5 h60
  text "Top Overlay" at 10217.76,6967.5 h60
  text "Top Solder" at 10217.76,6847.5 h60
  text "Solder Resist" at 11147.5,6847.5 h60
  text "0.40mil" at 12007.27,6847.5 h60
  text "3.5" at 12657.1,6847.5 h60
  text "1" at 9807.84,6727.5 h60
  text "Top Layer" at 10217.76,6727.5 h60
  text "2.80mil" at 12007.27,6727.5 h60
  text "Dielectric1" at 10217.76,6607.5 h60
  text "FR-4 High Tg" at 11147.5,6607.5 h60
  text "55.60mil" at 12007.27,6607.5 h60
  text "4.8" at 12657.1,6607.5 h60
  text "2" at 9807.84,6487.5 h60
  text "Bottom Layer" at 10217.76,6487.5 h60
  text "2.80mil" at 12007.27,6487.5 h60
  text "Bottom Solder" at 10217.76,6367.5 h60
  text "Solder Resist" at 11147.5,6367.5 h60
  text "0.40mil" at 12007.27,6367.5 h60
  text "3.5" at 12657.1,6367.5 h60
  text "Bottom Overlay" at 10217.76,6247.5 h60
  text ".Layer_Name" at 577,-858.49 h60
M13 Component Bodies Top:
  text ".Layer_Name" at 577,-858.49 h60
M14 Component Bodies Bottom:
  text ".Layer_Name" at 577,-858.49 h60
M15 Courtyards Top:
  text ".Layer_Name" at 577,-858.49 h60
M16 Courtyards Bottom:
  text ".Layer_Name" at 577,-858.49 h60
Drill Drawing:
  drawing of 158 lines, arcs and shapes, not listed
  text "Symbol" at 9196.82,6111.32 h72
  text "Quantity" at 9497.39,6111.32 h72
  text "Finished Hole Size" at 9829.39,6111.32 h72
  text "Plated" at 10465.95,6111.32 h72
  text "Hole Type" at 10725.09,6111.32 h72
  text "411" at 9497.39,5987 h60
  text "16.00mil (0.406mm)" at 9829.39,5987 h60
  text "PTH" at 10465.95,5987 h60
  text "Round" at 10725.09,5987 h60
  text "27" at 9497.39,5862.68 h60
  text "40.00mil (1.016mm)" at 9829.39,5862.68 h60
  text "PTH" at 10465.95,5862.68 h60
  text "Round" at 10725.09,5862.68 h60
  text "4" at 9497.39,5738.36 h60
  text "43.31mil (1.100mm)" at 9829.39,5738.36 h60
  text "PTH" at 10465.95,5738.36 h60
  text "Round" at 10725.09,5738.36 h60
  text "2" at 9497.39,5614.04 h60
  text "51.18mil (1.300mm)" at 9829.39,5614.04 h60
  text "PTH" at 10465.95,5614.04 h60
  text "Round" at 10725.09,5614.04 h60
  text "2" at 9497.39,5489.72 h60
  text "57.09mil (1.450mm)" at 9829.39,5489.72 h60
  text "PTH" at 10465.95,5489.72 h60
  text "Round" at 10725.09,5489.72 h60
  text "12" at 9497.39,5365.4 h60
  text "59.02mil (1.499mm)" at 9829.39,5365.4 h60
  text "PTH" at 10465.95,5365.4 h60
  text "Round" at 10725.09,5365.4 h60
  text "6" at 9497.39,5241.08 h60
  text "59.06mil (1.500mm)" at 9829.39,5241.08 h60
  text "PTH" at 10465.95,5241.08 h60
  text "Round" at 10725.09,5241.08 h60
  text "16" at 9497.39,5116.76 h60
  text "63.00mil (1.600mm)" at 9829.39,5116.76 h60
  text "PTH" at 10465.95,5116.76 h60
  text "Round" at 10725.09,5116.76 h60
  text "4" at 9497.39,4992.44 h60
  text "64.96mil (1.650mm)" at 9829.39,4992.44 h60
  text "PTH" at 10465.95,4992.44 h60
  text "Round" at 10725.09,4992.44 h60
  text "B" at 9171.54,4982.45 h55.25
  text "6" at 9497.39,4868.12 h60
  text "75.00mil (1.905mm)" at 9829.39,4868.12 h60
  text "PTH" at 10465.95,4868.12 h60
  text "Round" at 10725.09,4868.12 h60
  text "10" at 9497.39,4743.8 h60
  text "86.61mil (2.200mm)" at 9829.39,4743.8 h60
  text "PTH" at 10465.95,4743.8 h60
  text "Round" at 10725.09,4743.8 h60
  text "6" at 9497.39,4619.48 h60
  text "125.00mil (3.175mm)" at 9829.39,4619.48 h60
  text "PTH" at 10465.95,4619.48 h60
  text "Round" at 10725.09,4619.48 h60
  text "1" at 9497.39,4495.16 h60
  text "125.98mil (3.200mm)" at 9829.39,4495.16 h60
  text "PTH" at 10465.95,4495.16 h60
  text "Round" at 10725.09,4495.16 h60
  text "3" at 9497.39,4370.84 h60
  text "270.00mil (6.858mm)" at 9829.39,4370.84 h60
  text "PTH" at 10465.95,4370.84 h60
  text "Round" at 10725.09,4370.84 h60
  text "510 Total" at 9497.39,4246.52 h60
  text ".Layer_Name" at 577,-858.49 h60

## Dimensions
0,0 to 6400,0 on M2 Board Dimensions
0,0 to 0,3655 on M2 Board Dimensions
0,-400 to 1000,-400 on M2 Board Dimensions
